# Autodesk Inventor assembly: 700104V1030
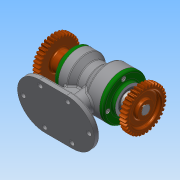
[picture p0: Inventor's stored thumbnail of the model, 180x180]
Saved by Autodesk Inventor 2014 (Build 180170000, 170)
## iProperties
Created: 2020-01
Part Number: 700104V1030
Document SubType Name: Assembly
Designer: net
Author: net
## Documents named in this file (13)
- C:\Users\net\Desktop\700104V1030\700104V1030.iam
- C:\Users\net\Desktop\700104V1030\700104V1030.ipt
- C:\Users\net\AppData\Local\Microsoft\Windows\Temporary Internet Files\Content.IE5\7TT6533R\베어링_6205[1].ipt
- C:\Users\net\AppData\Local\Microsoft\Windows\Temporary Internet Files\Content.IE5\C420WJO5\앞커버[1].ipt
- C:\Users\net\AppData\Local\Microsoft\Windows\Temporary Internet Files\Content.IE5\XAPV6VLY\오일_실_25_38_8[1].ipt
- C:\Users\net\AppData\Local\Microsoft\Windows\Temporary Internet Files\Content.IE5\7TT6533R\베어링_6203[1].ipt
- C:\Users\net\AppData\Local\Microsoft\Windows\Temporary Internet Files\Content.IE5\MOCD6Z2Z\뒤커버[1].ipt
- C:\Users\net\AppData\Local\Microsoft\Windows\Temporary Internet Files\Content.IE5\C420WJO5\오일_실_17_30_8[1].ipt
- C:\Users\net\AppData\Local\Microsoft\Windows\Temporary Internet Files\Content.IE5\XAPV6VLY\볼트_M4[1].ipt
- C:\Users\net\AppData\Local\Microsoft\Windows\Temporary Internet Files\Content.IE5\7TT6533R\축[1].ipt
- C:\Users\net\AppData\Local\Microsoft\Windows\Temporary Internet Files\Content.IE5\C420WJO5\키_5_x_5_x_18[1].ipt
- C:\Users\net\AppData\Local\Microsoft\Windows\Temporary Internet Files\Content.IE5\MOCD6Z2Z\스퍼기어[1].ipt
- C:\Users\net\AppData\Local\Microsoft\Windows\Temporary Internet Files\Content.IE5\XAPV6VLY\멈춤나사_M3[1].ipt
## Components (1 placed, 1 different names)
1. 700104V1030:1
